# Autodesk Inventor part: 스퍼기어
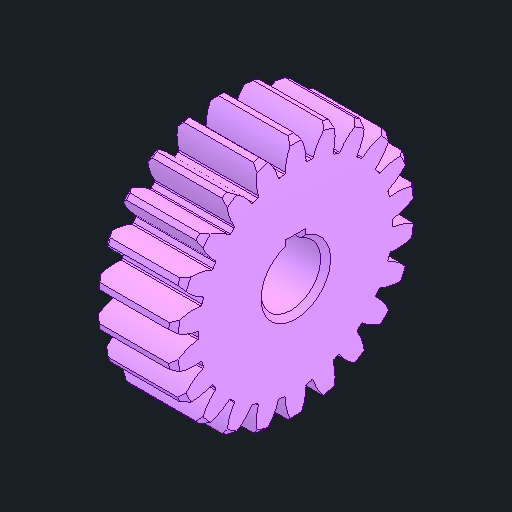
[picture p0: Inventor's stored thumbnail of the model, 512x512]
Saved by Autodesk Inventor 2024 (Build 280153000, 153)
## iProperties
Created: 2025-02
Part Number: 스퍼기어
Material: 강철, 합금
Document SubType Name: Modeling
Designer: kh_501
Density: 7.73 g/cm^3
Appearance: 기본값
Author: jhkim
Sending System: Autodesk Inventor 2025
Preprocessor: ST-DEVELOPER v20
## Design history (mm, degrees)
node "스퍼기어1"
node "솔리드2"
node "솔리드1"
